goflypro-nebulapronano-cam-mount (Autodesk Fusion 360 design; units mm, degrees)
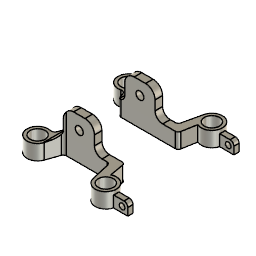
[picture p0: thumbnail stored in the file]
sketch "Skizze1" plane through (0, 0, 0) normal (0, 0, 1) x axis (1, 0, 0)
  line L1 (-7.919, 4) -> (-8.3877, 2.6607)
  line L2 (8.1804, 4) -> (8.4701, 2.3448)
  line L3 (8.7886, 0.5244) -> (8.4701, 2.3448)
  line L4 (-8.493, 2.3599) -> (-8.3877, 2.6607)
  line L5 (6, 3) -> (-6, 3)
  line L6 (8.0054, 5) -> (-7.569, 5)
  line L7 (-7.569, 5) -> (-7.919, 4)
  line L8 (8.0054, 5) -> (8.1804, 4)
  line L9 (-7.3537, -0.915) -> (-6, 3)
  line L10 (7.2688, -2.6169) -> (6, 3)
  line L11 (-6, 5) -> (-6, 3)
  line L12 (2, 5) -> (2, 3)
  circle C1 centre (-10, 0) radius 2
  circle C2 centre (10, -2) radius 2
  circle C3 centre (-10, 0) radius 2.8
  circle C4 centre (10, -2) radius 2.8
  point P10 (8.7886, 0.5244)
  point P11 (-8.493, 2.3599)
  point P15 (-7.3537, -0.915)
  point P17 (7.2688, -2.6169)
  point P18 (-6, 5)
  point P19 (2, 3)
  point P20 (2, 5)
  concentric C1 C3
  concentric C2 C4
  parallel L1 L4
  parallel L2 L3
  coincident C4 P10
  coincident C3 P11
  parallel L1 L7
  parallel L2 L8
  coincident C3 P15
  tangent C3 L9
  coincident C4 P17
  tangent C4 L10
  coincident L6 P18
  perpendicular L6 L11
  coincident L5 P19
  coincident L6 P20
  perpendicular L6 L12
  dimension "d1" diameter C1 = 4
  dimension "d2" diameter C2 = 4
  dimension "d3" diameter C3 = 5.6
  dimension "d4" diameter C4 = 5.6
extrude "Extrusion1" new body sketch "Skizze1" along normal blind 4 bodies "GoFlyPro - NebulaProNano - cam mount - left"
extrude "Extrusion5" add sketch "Skizze1" profile of L5 L6 L11 L12 along normal blind 11
sketch "Skizze2" plane through (0, 5, 0) normal (0, -1, 0) x axis (1, 0, 0)
  line L1 (-7.3847, 0) -> (10, 0)
  line L2 (10, 0) -> (10, -6)
  line L3 (10, -6) -> (-7.3847, -6)
  line L4 (-7.3847, -6) -> (-7.3847, 0)
  line L5 (6.5, 0) -> (-6.5, 0)
  line L6 (-6.5, 8) -> (6.5, 8)
  line L7 (6.5, 8) -> (6.5, 0)
  line L8 (-6.5, 0) -> (-6.5, 8)
  line L9 (-7.919, 0) -> (8.1804, 0)
  line L10 (-7.919, 8) -> (-7.919, 0)
  line L11 (8.1804, 8) -> (-7.919, 8)
  line L12 (8.1804, 0) -> (8.1804, 8)
  line L13 (-7.569, 0) -> (8.0054, 0)
  line L14 (-6, 4) -> (-7.569, 4)
  line L15 (8.0054, 0) -> (8.0054, 4)
  line L16 (-7.569, 4) -> (-7.569, 0)
  line L17 (-6, 11) -> (-6, 4)
  line L18 (2, 11) -> (-6, 11)
  line L19 (2, 4) -> (2, 11)
  line L20 (8.0054, 4) -> (2, 4)
  circle C1 centre (-2, 7.5) radius 1.05
  dimension "d8" diameter C1 = 2.1
extrude "Extrusion2" cut sketch "Skizze2" profile of C1 along normal blind 2
fillet "Abrundung7" radius 1
fillet "Abrundung11" radius 0.8
fillet "Abrundung12" radius 0.8
work_plane "Arbeitsebene" AlongDistance 12
fillet "Abrundung13" radius 2.5
fillet "Abrundung14" radius 1.5
fillet "Abrundung15" radius 2
sketch "Skizze3" plane through (0, 0, 0) normal (0, 0, 1) x axis (1, 0, 0)
  line L1 (12.5, -2.7) -> (16.5, -2.7)
  line L2 (12.5, -1.3) -> (12.5, -2.7)
  line L3 (16.5, -1.3) -> (12.5, -1.3)
  line L4 (16.5, -2.7) -> (16.5, -1.3)
  horizontal L1
  vertical L2
  horizontal L3
  vertical L4
extrude "Extrusion6" add sketch "Skizze3" along normal blind 3
sketch "Skizze4" plane through (0, -2.7, 0) normal (0, -1, 0) x axis (1, 0, 0)
  line L1 (12.7111, 0) -> (12.7111, 3)
  line L2 (16.5, 0) -> (12.7111, 0)
  line L3 (16.5, 3) -> (16.5, 0)
  line L4 (12.7111, 3) -> (16.5, 3)
  circle C1 centre (15, 1.5) radius 0.75
  dimension "d62" diameter C1 = 1.5
extrude "Extrusion7" cut sketch "Skizze4" profile of C1 against normal blind 2
fillet "Abrundung16" radius 1
mirror "Spiegeln" mirrorStitchTolerance 0.1 bodies "GoFlyPro - NebulaProNano - cam mount - right"
named bodies: "GoFlyPro - NebulaProNano - cam mount - left", "GoFlyPro - NebulaProNano - cam mount - right"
